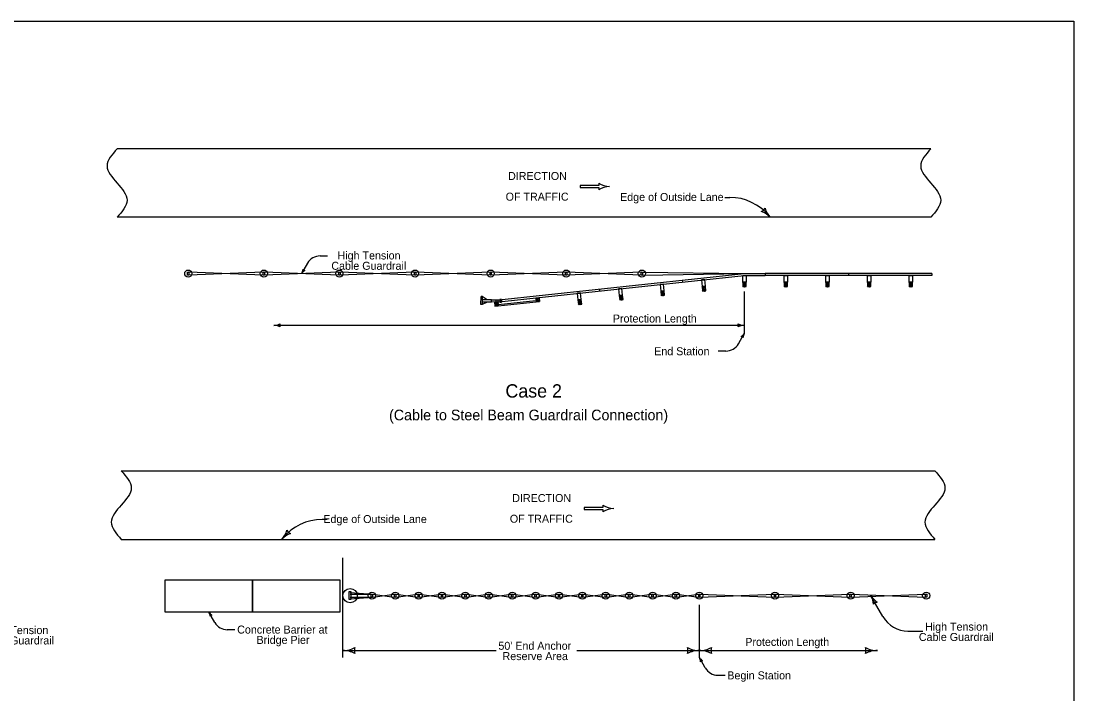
# Model space of a CAD drawing. Extents: x 10133 to 81668, y 7924 to 11018.
# Drawn here: x 11688 to 13268, y 8935 to 9944 of the extents above; entities that cross this region are included whole.
import ezdxf

# ---------------------------------------------------------------- set-up
doc = ezdxf.new("R2010")
doc.units = 0
for name, color, linetype in [('dsnCellElements', 7, 'Continuous'), ('DsnShtRevisedText', 7, 'Continuous'), ('dsnStdDimension', 7, 'Continuous'), ('Level 2', 7, 'Continuous'), ('Level 8', 7, 'Continuous'), ('SheetBorder', 7, 'Continuous')]:
    doc.layers.add(name, color=color, linetype=linetype)

msp = doc.modelspace()

# ---------------------------------------------------------------- linework, layer by layer
at = {"layer": 'dsnCellElements'}
for p, q in [((12051.5, 9562.9), (11940, 9567.4)), ((12051.5, 9567.4), (11940, 9562.9)), ((12164.9, 9562.9), (12053.4, 9567.4)), ((12164.9, 9567.4), (12053.4, 9562.9)), ((12278.3, 9562.9), (12166.8, 9567.4)), ((12278.3, 9567.4), (12166.8, 9562.9)), ((12391.7, 9562.9), (12280.2, 9567.4)), ((12391.7, 9567.4), (12280.2, 9562.9)), ((12505.1, 9562.9), (12393.6, 9567.4)), ((12505.1, 9567.4), (12393.6, 9562.9)), ((12618.5, 9562.9), (12507, 9567.4)), ((12618.5, 9567.4), (12507, 9562.9)), ((12620.4, 9567.5), (12773.1, 9565.2)), ((12620.4, 9562.9), (12773.1, 9565.2)), ((12181.8, 9086.8), (12215.3, 9084.4)), ((12181.8, 9084.4), (12213.5, 9084.4)), ((12215.3, 9084.4), (12248.5, 9079.9)), ((12215.3, 9079.9), (12248.5, 9084.4)), ((12250.4, 9084.4), (12283.6, 9079.9)), ((12250.4, 9079.9), (12283.6, 9084.4)), ((12285.5, 9084.4), (12318.7, 9079.9)), ((12285.5, 9079.9), (12318.7, 9084.4)), ((12320.6, 9084.4), (12353.8, 9079.9)), ((12320.6, 9079.9), (12353.8, 9084.4)), ((12355.7, 9084.4), (12388.9, 9079.9)), ((12355.7, 9079.9), (12388.9, 9084.4)), ((12390.8, 9084.4), (12424, 9079.9)), ((12390.8, 9079.9), (12424, 9084.4)), ((12425.9, 9079.9), (12459.1, 9084.4)), ((12425.9, 9084.4), (12459.1, 9079.9)), ((12461, 9084.4), (12494.2, 9079.9)), ((12461, 9079.9), (12494.2, 9084.4)), ((12496.1, 9084.4), (12529.3, 9079.9)), ((12496.1, 9079.9), (12529.3, 9084.4)), ((12531.1, 9084.4), (12564.4, 9079.9)), ((12531.1, 9079.9), (12564.4, 9084.4)), ((12566.3, 9084.4), (12599.4, 9079.9)), ((12566.3, 9079.9), (12599.4, 9084.4)), ((12601.3, 9084.4), (12634.6, 9079.9)), ((12601.3, 9079.9), (12634.6, 9084.4)), ((12636.5, 9084.4), (12669.6, 9079.9)), ((12636.5, 9079.9), (12669.6, 9084.4)), ((12671.5, 9084.4), (12704.8, 9079.9)), ((12671.5, 9079.9), (12704.8, 9084.4)), ((12706.6, 9084.4), (12818.2, 9079.9)), ((12706.6, 9079.9), (12818.2, 9084.4)), ((12820, 9084.4), (12931.6, 9079.9)), ((12820, 9079.9), (12931.6, 9084.4)), ((12933.4, 9084.4), (13045, 9079.9)), ((12933.4, 9079.9), (13045, 9084.4)), ((12181.8, 9079.9), (12213.5, 9079.9)), ((12181.8, 9077.5), (12215.3, 9079.9))]:
    msp.add_line(p, q, dxfattribs=at)
for points in [[(11940, 9567.4), (11940, 9562.9), (11938.1, 9562.9), (11938.1, 9567.4)], [(12053.4, 9567.4), (12053.4, 9562.9), (12051.5, 9562.9), (12051.5, 9567.4)], [(12053.4, 9567.4), (12053.4, 9562.9), (12051.5, 9562.9), (12051.5, 9567.4)], [(12166.8, 9567.4), (12166.8, 9562.9), (12164.9, 9562.9), (12164.9, 9567.4)], [(12166.8, 9567.4), (12166.8, 9562.9), (12164.9, 9562.9), (12164.9, 9567.4)], [(12280.2, 9567.4), (12280.2, 9562.9), (12278.3, 9562.9), (12278.3, 9567.4)], [(12280.2, 9567.4), (12280.2, 9562.9), (12278.3, 9562.9), (12278.3, 9567.4)], [(12393.6, 9567.4), (12393.6, 9562.9), (12391.7, 9562.9), (12391.7, 9567.4)], [(12393.6, 9567.4), (12393.6, 9562.9), (12391.7, 9562.9), (12391.7, 9567.4)], [(12507, 9567.4), (12507, 9562.9), (12505.1, 9562.9), (12505.1, 9567.4)], [(12507, 9567.4), (12507, 9562.9), (12505.1, 9562.9), (12505.1, 9567.4)], [(12620.4, 9567.4), (12620.4, 9562.9), (12618.5, 9562.9), (12618.5, 9567.4)], [(12180.6, 9076.1), (12180.6, 9088.1), (12183, 9088.1), (12183, 9076.1)], [(12213.5, 9079.9), (12213.5, 9084.4), (12215.3, 9084.4), (12215.3, 9079.9)], [(12248.5, 9079.9), (12248.5, 9084.4), (12250.4, 9084.4), (12250.4, 9079.9)], [(12283.7, 9079.9), (12283.7, 9084.4), (12285.5, 9084.4), (12285.5, 9079.9)], [(12318.7, 9079.9), (12318.7, 9084.4), (12320.6, 9084.4), (12320.6, 9079.9)], [(12353.9, 9079.9), (12353.9, 9084.4), (12355.7, 9084.4), (12355.7, 9079.9)], [(12388.9, 9079.9), (12388.9, 9084.4), (12390.8, 9084.4), (12390.8, 9079.9)], [(12424, 9079.9), (12424, 9084.4), (12425.9, 9084.4), (12425.9, 9079.9)], [(12459.1, 9079.9), (12459.1, 9084.4), (12461, 9084.4), (12461, 9079.9)], [(12494.2, 9079.9), (12494.2, 9084.4), (12496.1, 9084.4), (12496.1, 9079.9)], [(12529.3, 9079.9), (12529.3, 9084.4), (12531.1, 9084.4), (12531.1, 9079.9)], [(12564.4, 9079.9), (12564.4, 9084.4), (12566.3, 9084.4), (12566.3, 9079.9)], [(12599.4, 9079.9), (12599.4, 9084.4), (12601.3, 9084.4), (12601.3, 9079.9)], [(12634.6, 9079.9), (12634.6, 9084.4), (12636.5, 9084.4), (12636.5, 9079.9)], [(12669.6, 9079.9), (12669.6, 9084.4), (12671.5, 9084.4), (12671.5, 9079.9)], [(12704.8, 9079.9), (12704.8, 9084.4), (12706.6, 9084.4), (12706.6, 9079.9)], [(12704.8, 9079.9), (12704.8, 9084.4), (12706.6, 9084.4), (12706.6, 9079.9)], [(12818.2, 9079.9), (12818.2, 9084.4), (12820, 9084.4), (12820, 9079.9)], [(12818.2, 9079.9), (12818.2, 9084.4), (12820, 9084.4), (12820, 9079.9)], [(12931.6, 9079.9), (12931.6, 9084.4), (12933.4, 9084.4), (12933.4, 9079.9)], [(12931.6, 9079.9), (12931.6, 9084.4), (12933.4, 9084.4), (12933.4, 9079.9)], [(13045, 9079.9), (13045, 9084.4), (13046.8, 9084.4), (13046.8, 9079.9)]]:
    msp.add_lwpolyline(points, close=True, dxfattribs=at)
for centre, radius in [((11939, 9565.2), 5.32), ((12052.4, 9565.2), 5.32), ((12052.4, 9565.2), 5.32), ((12165.8, 9565.2), 5.32), ((12165.8, 9565.2), 5.32), ((12279.2, 9565.2), 5.32), ((12279.2, 9565.2), 5.32), ((12392.6, 9565.2), 5.32), ((12392.6, 9565.2), 5.32), ((12506, 9565.2), 5.32), ((12506, 9565.2), 5.32), ((12619.4, 9565.2), 5.32), ((12181.8, 9082.1), 10.8), ((12214.4, 9082.1), 5.32), ((12249.4, 9082.1), 5.32), ((12284.6, 9082.1), 5.32), ((12319.6, 9082.1), 5.32), ((12354.8, 9082.1), 5.32), ((12389.8, 9082.1), 5.32), ((12425, 9082.1), 5.32), ((12460, 9082.1), 5.32), ((12495.2, 9082.1), 5.32), ((12530.2, 9082.1), 5.32), ((12565.3, 9082.1), 5.32), ((12600.4, 9082.1), 5.32), ((12635.5, 9082.1), 5.32), ((12670.6, 9082.1), 5.32), ((12705.7, 9082.1), 5.32), ((12705.7, 9082.1), 5.32), ((12819.1, 9082.1), 5.32), ((12819.1, 9082.1), 5.32), ((12932.5, 9082.1), 5.32), ((12932.5, 9082.1), 5.32), ((13045.9, 9082.1), 5.32)]:
    msp.add_circle(centre, radius, dxfattribs=at)
at = {"layer": 'DsnShtRevisedText'}
for p, q in [((12554.8, 9697.4), (12526.9, 9697.4)), ((12526.9, 9697.4), (12526.9, 9694.4)), ((12554.8, 9701), (12554.8, 9697.4)), ((12526.9, 9694.4), (12554.8, 9694.4)), ((12554.8, 9694.4), (12554.8, 9690.8)), ((12571, 9695.9), (12571, 9695.9)), ((12743.9, 9679.5), (12751.3, 9679.5)), ((12136.8, 9591.6), (12148.1, 9591.6)), ((12118, 9580.8), (12109.1, 9565.2)), ((12773.1, 9538.1), (12773.1, 9475.5)), ((12750.6, 9487.5), (12067.6, 9487.5)), ((12773.1, 9487.5), (12750.6, 9487.5)), ((12764.2, 9459.8), (12773.1, 9475.5)), ((12745.4, 9449), (12734.1, 9449)), ((12561.1, 9214.4), (12533.1, 9214.4)), ((12533.1, 9214.4), (12533.1, 9211.3)), ((12533.1, 9211.3), (12561.1, 9211.3)), ((12561.1, 9217.9), (12561.1, 9214.4)), ((12561.1, 9211.3), (12561.1, 9207.8)), ((12577.3, 9212.8), (12577.3, 9212.8)), ((12147.4, 9196.4), (12139.9, 9196.4)), ((12171, 8989.2), (12171, 9138.7)), ((12980.9, 9050.6), (12963.1, 9081.9)), ((12705.7, 8989.2), (12705.7, 9068.5)), ((11978.8, 9041.9), (11969.9, 9057.5)), ((11997.6, 9031.1), (12008.8, 9031.1)), ((13018.5, 9029), (13041, 9029)), ((12171, 8999.8), (12401.1, 8999.8)), ((12522.1, 8999.8), (12748.6, 8999.8)), ((12714.6, 8973.6), (12705.7, 8989.2)), ((12748.6, 8999.8), (12916.6, 8999.8)), ((12916.6, 8999.8), (12972.8, 8999.8)), ((12733.4, 8962.8), (12744.6, 8962.8))]:
    msp.add_line(p, q, dxfattribs=at)
for centre, radius, start, end in [((12572.3, 9728.6), 32.7, 237.618, 267.648), ((12572.3, 9663.2), 32.7, 92.352, 122.382), ((12751.3, 9603.3), 76.2, 39.0106, 90), ((12793.3, 9669.5), 12.5, 295.2639, 330.7306), ((12788.1, 9627.5), 32.4, 42.9973, 71.0698), ((12835.5, 9671.7), 32.4, 194.9248, 222.9973), ((12136.8, 9569.9), 21.8, 90, 149.7757), ((12097.4, 9572), 13.6, 329.7686, 357.8411), ((12114.9, 9575), 5.25, 222.0353, 257.502), ((12120.9, 9558.3), 13.6, 121.6962, 149.7686), ((12067.6, 9506.6), 19.1, 270, 298.0725), ((12067.6, 9468.3), 19.1, 61.9275, 90), ((12083.6, 9487.5), 7.39, 162.2666, 197.7334), ((12757, 9487.5), 7.39, 342.2666, 17.7333), ((12773.1, 9506.6), 19.1, 241.9275, 270), ((12773.1, 9468.3), 19.1, 90, 118.0725), ((12761.3, 9482.3), 13.6, 301.6962, 329.7686), ((12767.3, 9465.6), 5.25, 42.0353, 77.502), ((12784.8, 9468.6), 13.6, 149.7686, 177.8411), ((12745.4, 9470.8), 21.8, 270, 329.7757), ((12578.6, 9245.6), 32.7, 237.618, 267.648), ((12578.6, 9180.1), 32.7, 92.352, 122.382), ((12139.9, 9120.2), 76.2, 90, 140.9894), ((12055.7, 9188.6), 32.4, 317.0027, 345.0752), ((12097.9, 9186.4), 12.5, 209.2694, 244.7361), ((12103.1, 9144.5), 32.4, 108.9302, 137.0027), ((12939.6, 9068.2), 27.2, 2.1589, 30.2314), ((12986.7, 9095.6), 27.2, 210.2314, 238.3038), ((12974.6, 9062.2), 10.5, 102.498, 137.9647), ((11958.2, 9050.7), 13.6, 2.1589, 30.2314), ((11981.7, 9064.4), 13.6, 210.2314, 238.3038), ((11975.6, 9047.7), 5.25, 102.498, 137.9647), ((13018.5, 9072.5), 43.5, 210.2243, 270), ((11997.6, 9052.8), 21.8, 210.2243, 270), ((12171, 9038), 38.3, 270, 298.0725), ((12203, 8999.8), 14.8, 162.2666, 197.7334), ((12673.6, 8999.8), 14.8, 342.2666, 17.7333), ((12705.7, 9038), 38.3, 241.9275, 270), ((12705.7, 9038), 38.3, 270, 298.0725), ((12737.8, 8999.8), 14.8, 162.2666, 197.7334), ((12940.7, 8999.8), 14.8, 342.2666, 17.7333), ((12972.7, 9038), 38.3, 241.9275, 270), ((12171, 8961.5), 38.3, 61.9275, 90), ((12705.7, 8961.5), 38.3, 90, 118.0725), ((12705.7, 8961.5), 38.3, 61.9275, 90), ((12693.9, 8982.4), 13.6, 2.1589, 30.2314), ((12717.4, 8996.1), 13.6, 210.2314, 238.3038), ((12972.7, 8961.5), 38.3, 90, 118.0725), ((12711.4, 8979.4), 5.25, 102.498, 137.9647), ((12733.4, 8984.6), 21.8, 210.2243, 270)]:
    msp.add_arc(centre, radius, start, end, dxfattribs=at)
at = {"layer": 'dsnStdDimension'}
for p, q in [((13052.7, 9752.5), (11832.2, 9752.5)), ((13052.7, 9649.6), (11832.2, 9649.6)), ((11838.5, 9269.4), (13059, 9269.4)), ((11838.5, 9166.5), (13059, 9166.5))]:
    msp.add_line(p, q, dxfattribs=at)
for points in [[(11904.5, 9106), (12035.4, 9106), (12035.4, 9057.5), (11904.5, 9057.5)], [(12035.4, 9106), (12166.3, 9106), (12166.3, 9057.5), (12035.4, 9057.5)]]:
    msp.add_lwpolyline(points, close=True, dxfattribs=at)
for points in [[(11832.2, 9752.5), (11817.2, 9726.8), (11832.2, 9701), (11847.2, 9675.3), (11832.2, 9649.6)], [(13052.7, 9752.5), (13037.7, 9726.8), (13052.7, 9701), (13067.7, 9675.3), (13052.7, 9649.6)], [(11838.5, 9269.4), (11853.5, 9243.7), (11838.5, 9218), (11823.5, 9192.3), (11838.5, 9166.5)], [(13059, 9269.4), (13074, 9243.7), (13059, 9218), (13044, 9192.3), (13059, 9166.5)]]:
    msp.add_spline(points, degree=3, dxfattribs=at)
at = {"layer": 'Level 2'}
for p, q in [((12400.2, 9525.2), (12773.1, 9565.2)), ((12400.5, 9522.5), (12773.1, 9562.5)), ((12680, 9555.2), (12680.3, 9552.5)), ((12771, 9562.2), (12776, 9562.5)), ((12771, 9552.2), (12771, 9562.2)), ((12773.1, 9565.2), (12804.4, 9565.2)), ((12773.1, 9562.5), (12804.4, 9562.5)), ((12776, 9562.5), (12776, 9552.2)), ((12804.4, 9565.2), (12804.4, 9562.5)), ((12929.4, 9565.2), (12804.4, 9565.2)), ((12804.4, 9565.2), (12804.4, 9562.5)), ((12929.4, 9562.5), (12804.4, 9562.5)), ((12833.1, 9552.4), (12833.1, 9562.5)), ((12833.1, 9562.5), (12838.1, 9562.5)), ((12838.1, 9562.5), (12838.1, 9552.4)), ((12895.6, 9552.4), (12895.6, 9562.5)), ((12895.6, 9562.5), (12900.6, 9562.5)), ((12900.6, 9562.5), (12900.6, 9552.4)), ((12929.4, 9565.2), (12929.4, 9562.5)), ((13054.4, 9565.2), (12929.4, 9565.2)), ((12929.4, 9565.2), (12929.4, 9562.5)), ((13054.4, 9562.5), (12929.4, 9562.5)), ((12958.1, 9552.4), (12958.1, 9562.5)), ((12958.1, 9562.5), (12963.1, 9562.5)), ((12963.1, 9562.5), (12963.1, 9552.4)), ((13020.6, 9552.4), (13020.6, 9562.5)), ((13020.6, 9562.5), (13025.6, 9562.5)), ((13025.6, 9562.5), (13025.6, 9552.4)), ((13054.4, 9565.2), (13054.4, 9562.5)), ((12555.7, 9541.8), (12556, 9539.2)), ((12648.5, 9532.3), (12652.8, 9539.5)), ((12650.3, 9539.2), (12651, 9532.6)), ((12715.6, 9539.5), (12709.9, 9545.6)), ((12710.6, 9539), (12714.9, 9546.1)), ((12712.4, 9545.9), (12713.1, 9539.2)), ((12776, 9552.2), (12771, 9552.2)), ((12776, 9545.6), (12771, 9552.2)), ((12771, 9545.6), (12776, 9552.2)), ((12773.5, 9552.2), (12773.5, 9545.6)), ((12838.1, 9552.4), (12833.1, 9552.4)), ((12838.1, 9545.8), (12833.1, 9552.4)), ((12833.1, 9545.8), (12838.1, 9552.4)), ((12835.6, 9552.4), (12835.6, 9545.8)), ((12835.6, 9544.8), (12835.6, 9544.7)), ((12900.6, 9552.4), (12895.6, 9552.4)), ((12900.6, 9545.8), (12895.6, 9552.4)), ((12895.6, 9545.8), (12900.6, 9552.4)), ((12898.1, 9552.4), (12898.1, 9545.8)), ((12898.1, 9544.8), (12898.1, 9544.7)), ((12963.1, 9552.4), (12958.1, 9552.4)), ((12963.1, 9545.8), (12958.1, 9552.4)), ((12958.1, 9545.8), (12963.1, 9552.4)), ((12960.6, 9552.4), (12960.6, 9545.8)), ((12960.6, 9544.8), (12960.6, 9544.7)), ((13025.6, 9552.4), (13020.6, 9552.4)), ((13025.6, 9545.8), (13020.6, 9552.4)), ((13020.6, 9545.8), (13025.6, 9552.4)), ((13023.1, 9552.4), (13023.1, 9545.8)), ((13023.1, 9544.8), (13023.1, 9544.7)), ((12393.7, 9525.5), (12406.3, 9526)), ((12400.2, 9525.2), (12400.5, 9522.5)), ((12403.5, 9525.9), (12403.6, 9522.7)), ((12461.5, 9529), (12465.2, 9529.4)), ((12462.8, 9529.2), (12463.4, 9523.2)), ((12529.2, 9519.5), (12523.5, 9525.6)), ((12524.2, 9519), (12528.5, 9526.1)), ((12526, 9525.9), (12526.7, 9519.2)), ((12591.3, 9526.2), (12585.6, 9532.3)), ((12586.4, 9525.6), (12590.6, 9532.8)), ((12588.1, 9532.5), (12588.8, 9525.9)), ((12588.9, 9524.9), (12589, 9524.9)), ((12653.5, 9532.8), (12647.8, 9538.9)), ((12651.1, 9531.6), (12651.1, 9531.5)), ((12651.4, 9532.6), (12651.5, 9532.5)), ((12713.2, 9538.3), (12713.2, 9538.2)), ((12406.4, 9522.8), (12393.8, 9522.3)), ((12399.1, 9522.3), (12399.1, 9522.2)), ((12400.6, 9522.3), (12401.3, 9516.5)), ((12404, 9516.9), (12460.8, 9523)), ((12526.8, 9518.3), (12526.8, 9518.2))]:
    msp.add_line(p, q, dxfattribs=at)
for points in [[(12713.8, 9556.1), (12708.9, 9555.6), (12709.9, 9545.6), (12714.9, 9546.1)], [(12589.5, 9542.8), (12584.6, 9542.2), (12585.6, 9532.3), (12590.6, 9532.8)], [(12651.7, 9549.4), (12646.7, 9548.9), (12647.8, 9538.9), (12652.8, 9539.5)], [(12652.8, 9539.5), (12647.8, 9538.9), (12648.5, 9532.3), (12653.5, 9532.8)], [(12714.9, 9546.1), (12709.9, 9545.6), (12710.6, 9539), (12715.6, 9539.5)], [(12776, 9552.2), (12771, 9552.2), (12771, 9545.6), (12776, 9545.6)], [(12838.1, 9552.4), (12833.1, 9552.4), (12833.1, 9545.8), (12838.1, 9545.8)], [(12900.6, 9552.4), (12895.6, 9552.4), (12895.6, 9545.8), (12900.6, 9545.8)], [(12963.1, 9552.4), (12958.1, 9552.4), (12958.1, 9545.8), (12963.1, 9545.8)], [(13025.6, 9552.4), (13020.6, 9552.4), (13020.6, 9545.8), (13025.6, 9545.8)], [(12406.4, 9522.7), (12406.5, 9522.4), (12409, 9522.5), (12408.9, 9522.8), (12408.8, 9526.2), (12408.8, 9526.5), (12406.3, 9526.4), (12406.3, 9526.1)], [(12527.4, 9536.1), (12522.4, 9535.6), (12523.5, 9525.6), (12528.5, 9526.1)], [(12528.5, 9526.1), (12523.5, 9525.6), (12524.2, 9519), (12529.2, 9519.5)], [(12590.6, 9532.8), (12585.6, 9532.3), (12586.4, 9525.6), (12591.3, 9526.2)]]:
    msp.add_lwpolyline(points, close=True, dxfattribs=at)
for points in [[(12713.5, 9539.3), (12713.5, 9538.9), (12712.8, 9538.8), (12712.8, 9539.2)], [(12773.8, 9545.6), (12773.8, 9545.2), (12773.2, 9545.2), (12773.2, 9545.6)], [(12773.7, 9545.2), (12773.7, 9544.6), (12773.3, 9544.6), (12773.3, 9545.2)], [(12836, 9545.8), (12836, 9545.3), (12835.3, 9545.3), (12835.3, 9545.8)], [(12835.8, 9545.3), (12835.8, 9544.8), (12835.4, 9544.8), (12835.4, 9545.3)], [(12898.5, 9545.8), (12898.5, 9545.3), (12897.8, 9545.3), (12897.8, 9545.8)], [(12898.3, 9545.3), (12898.3, 9544.8), (12897.9, 9544.8), (12897.9, 9545.3)], [(12961, 9545.8), (12961, 9545.3), (12960.3, 9545.3), (12960.3, 9545.8)], [(12960.8, 9545.3), (12960.8, 9544.8), (12960.4, 9544.8), (12960.4, 9545.3)], [(13023.5, 9545.8), (13023.5, 9545.3), (13022.8, 9545.3), (13022.8, 9545.8)], [(13023.3, 9545.3), (13023.3, 9544.8), (13022.9, 9544.8), (13022.9, 9545.3)], [(12378.1, 9518.9), (12378.3, 9530.6)], [(12378.3, 9530.5), (12379.8, 9530.5), (12379.7, 9519), (12378.1, 9519.1)], [(12379.9, 9530.6), (12378.3, 9530.6)], [(12379.9, 9530.6), (12379.8, 9518.9)], [(12387.3, 9525.7), (12379.9, 9530.6)], [(12393.7, 9525.6), (12379.9, 9525.8)], [(12406.4, 9522.7), (12393.8, 9522.2), (12393.7, 9525.6), (12406.3, 9526.1)], [(12403.7, 9518.9), (12460.5, 9525)], [(12403.8, 9518.9), (12460.5, 9525)], [(12406.3, 9526.1), (12408.8, 9526.2), (12408.9, 9522.8), (12406.4, 9522.7)], [(12460.1, 9528.7), (12460.2, 9528.3)], [(12460.2, 9528.3), (12460.8, 9523)], [(12460.3, 9528.9), (12465.3, 9529.4)], [(12460.3, 9528.7), (12465.3, 9529.3)], [(12460.3, 9528.7), (12465.9, 9523.5)], [(12460.3, 9528.7), (12460.3, 9528.3)], [(12460.3, 9528.3), (12460.9, 9522.9)], [(12465.3, 9529.3), (12460.9, 9522.9)], [(12460.9, 9522.9), (12465.9, 9523.5)], [(12461, 9522.8), (12465.9, 9523.3)], [(12465.3, 9529.4), (12465.9, 9523.3)], [(12589.2, 9525.9), (12589.2, 9525.5), (12588.6, 9525.4), (12588.5, 9525.9)], [(12589.1, 9525.5), (12589.1, 9525), (12588.8, 9524.9), (12588.7, 9525.5)], [(12651.3, 9532.6), (12651.4, 9532.2), (12650.7, 9532.1), (12650.7, 9532.5)], [(12651.2, 9532.2), (12651.3, 9531.6), (12650.9, 9531.6), (12650.8, 9532.1)], [(12713.4, 9538.8), (12713.4, 9538.3), (12713, 9538.3), (12713, 9538.8)], [(12379.8, 9518.9), (12378.1, 9518.9)], [(12393.8, 9522.2), (12379.8, 9522.4)], [(12387.4, 9522.3), (12379.8, 9518.9)], [(12398.2, 9522.1), (12403.1, 9522.6)], [(12398.2, 9522.1), (12403.8, 9516.8)], [(12398.2, 9522.1), (12398.8, 9516.3)], [(12403.1, 9522.6), (12398.8, 9516.3)], [(12398.8, 9516.3), (12403.8, 9516.8)], [(12403.1, 9522.7), (12399.1, 9522.3)], [(12403.1, 9522.6), (12399.1, 9522.2)], [(12403.8, 9516.8), (12399.7, 9516.4)], [(12403.8, 9516.6), (12399.7, 9516.2)], [(12399.7, 9516.2), (12399.7, 9516.4)], [(12403.2, 9522.5), (12403.2, 9522.1)], [(12403.2, 9522.1), (12403.3, 9521.9)], [(12403.3, 9521.9), (12403.6, 9519.1)], [(12403.4, 9522.6), (12403.4, 9522.2)], [(12403.4, 9522.2), (12403.4, 9522)], [(12403.4, 9522), (12403.7, 9519.1)], [(12403.6, 9519.1), (12403.8, 9516.8)], [(12403.7, 9519.1), (12404, 9516.9)], [(12404, 9516.9), (12460.8, 9523)], [(12527, 9519.3), (12527.1, 9518.8), (12526.4, 9518.8), (12526.4, 9519.2)], [(12526.9, 9518.8), (12527, 9518.3), (12526.6, 9518.3), (12526.6, 9518.8)]]:
    msp.add_lwpolyline(points, dxfattribs=at)
for centre, radius, start, end in [((12460.4, 9528.7), 0.208, 96.1292, 186.1292), ((12403.2, 9522.5), 0.208, 6.1292, 96.1292), ((12403.2, 9522.5), 0.0517, 6.1292, 96.1292), ((12403.8, 9516.8), 0.208, 276.1292, 6.1292), ((12403.8, 9516.8), 0.0517, 276.1292, 6.1292), ((12461, 9523), 0.208, 186.1292, 276.1292)]:
    msp.add_arc(centre, radius, start, end, dxfattribs=at)
at = {"layer": 'SheetBorder'}
msp.add_lwpolyline([(10132.5, 9944), (13267.5, 9944), (13267.5, 7924), (10132.5, 7924)], close=True, dxfattribs=at)

# ---------------------------------------------------------------- texts
at = {"layer": 'DsnShtRevisedText'}
for s, p in [('DIRECTION', (12418.7, 9705.6)), ('OF TRAFFIC', (12415.1, 9674.6)), ('Edge of Outside Lane', (12586.8, 9674.1)), ('High Tension', (12162.9, 9586.4)), ('Cable Guardrail', (12153.6, 9570.9)), ('Protection Length', (12575.9, 9491.8)), ('End Station', (12637.9, 9442.7)), ('DIRECTION', (12425, 9222.5)), ('Edge of Outside Lane', (12141.6, 9191)), ('OF TRAFFIC', (12421.4, 9191.5)), ('High Tension', (11634.6, 9024.4)), ('Concrete Barrier at ', (12012.4, 9025.2)), ('High Tension', (13044.2, 9029.6)), ('Cable Guardrail', (11625.3, 9008.9)), ('Bridge Pier', (12041.5, 9009.7)), ('Protection Length', (12774.6, 9006.7)), ('Cable Guardrail', (13034.9, 9014.1)), ("50' End Anchor", (12404.2, 9000.9)), ('Reserve Area', (12410.4, 8985.4)), ('Begin Station', (12747.6, 8956.5))]:
    msp.add_text(s, height=12, dxfattribs=at).set_placement(p)
at = {"layer": 'Level 8'}
for s, height, p in [('Case 2', 20, (12414.8, 9379.2)), ('(Cable to Steel Beam Guardrail Connection)', 16, (12240.2, 9345.1))]:
    msp.add_text(s, height=height, dxfattribs=at).set_placement(p)

doc.saveas('drawing.dxf')
